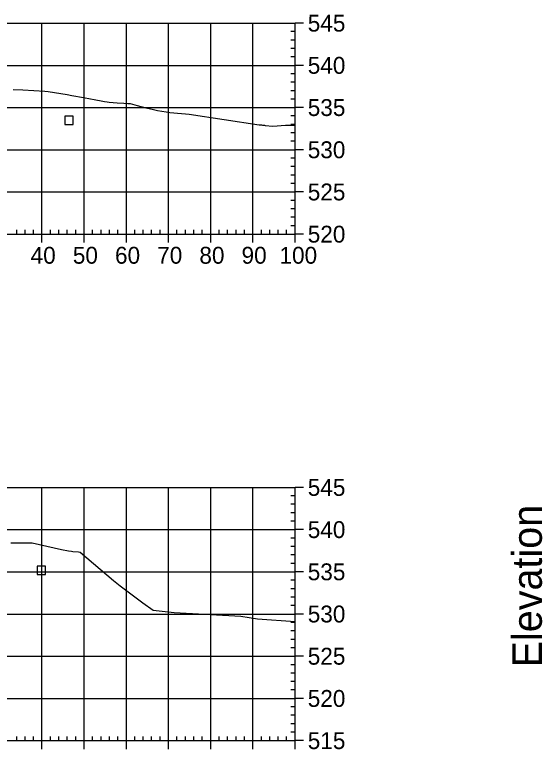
# Model space of a CAD drawing. Extents: x 704834 to 709892, y 372981 to 377533.
# Drawn here: x 707063.4 to 707188.5, y 377088.8 to 377262.8 of the extents above; entities that cross this region are included whole.
import ezdxf

# ---------------------------------------------------------------- set-up
doc = ezdxf.new("R2010")
doc.units = 0
for name, color, linetype in [('4', 7, 'Continuous'), ('57', 7, 'Continuous'), ('60', 7, 'Continuous'), ('Existing', 7, 'Continuous')]:
    doc.layers.add(name, color=color, linetype=linetype)

msp = doc.modelspace()

# ---------------------------------------------------------------- linework, layer by layer
at = {"layer": '4'}
for points in [[(707075.29, 377236.8), (707077.29, 377236.8), (707077.29, 377238.8), (707075.29, 377238.8)], [(707068.74, 377130.17), (707070.74, 377130.17), (707070.74, 377132.17), (707068.74, 377132.17)]]:
    msp.add_lwpolyline(points, close=True, dxfattribs=at)
at = {"layer": '57'}
for p, q in [((706929.91, 377260.82), (707129.91, 377260.82)), ((707069.91, 377210.82), (707069.91, 377260.82)), ((707079.91, 377210.82), (707079.91, 377260.82)), ((707089.91, 377210.82), (707089.91, 377260.82)), ((707099.91, 377210.82), (707099.91, 377260.82)), ((707109.91, 377210.82), (707109.91, 377260.82)), ((707119.91, 377210.82), (707119.91, 377260.82)), ((707129.91, 377210.82), (707129.91, 377260.82)), ((707129.91, 377210.82), (707129.91, 377260.82)), ((707131.91, 377260.82), (707129.91, 377260.82)), ((707129.91, 377258.82), (707128.91, 377258.82)), ((707129.91, 377256.82), (707128.91, 377256.82)), ((707129.91, 377254.82), (707128.91, 377254.82)), ((707129.91, 377252.82), (707128.91, 377252.82)), ((706929.91, 377250.82), (707129.91, 377250.82)), ((707131.91, 377250.82), (707129.91, 377250.82)), ((707129.91, 377248.82), (707128.91, 377248.82)), ((707129.91, 377246.82), (707128.91, 377246.82)), ((707129.91, 377244.82), (707128.91, 377244.82)), ((707129.91, 377242.82), (707128.91, 377242.82)), ((706929.91, 377240.82), (707129.91, 377240.82)), ((707131.91, 377240.82), (707129.91, 377240.82)), ((707129.91, 377238.82), (707128.91, 377238.82)), ((707129.91, 377236.82), (707128.91, 377236.82)), ((707129.91, 377234.82), (707128.91, 377234.82)), ((707129.91, 377232.82), (707128.91, 377232.82)), ((706929.91, 377230.82), (707129.91, 377230.82)), ((707131.91, 377230.82), (707129.91, 377230.82)), ((707129.91, 377228.82), (707128.91, 377228.82)), ((707129.91, 377226.82), (707128.91, 377226.82)), ((707129.91, 377224.82), (707128.91, 377224.82)), ((707129.91, 377222.82), (707128.91, 377222.82)), ((706929.91, 377220.82), (707129.91, 377220.82)), ((707131.91, 377220.82), (707129.91, 377220.82)), ((707129.91, 377218.82), (707128.91, 377218.82)), ((707129.91, 377216.82), (707128.91, 377216.82)), ((707129.91, 377214.82), (707128.91, 377214.82)), ((707129.91, 377212.82), (707128.91, 377212.82)), ((706929.91, 377210.82), (707129.91, 377210.82)), ((706929.91, 377210.82), (707129.91, 377210.82)), ((707063.91, 377210.82), (707063.91, 377211.82)), ((707065.91, 377210.82), (707065.91, 377211.82)), ((707067.91, 377210.82), (707067.91, 377211.82)), ((707069.91, 377208.82), (707069.91, 377210.82)), ((707071.91, 377210.82), (707071.91, 377211.82)), ((707073.91, 377210.82), (707073.91, 377211.82)), ((707075.91, 377210.82), (707075.91, 377211.82)), ((707077.91, 377210.82), (707077.91, 377211.82)), ((707079.91, 377208.82), (707079.91, 377210.82)), ((707081.91, 377210.82), (707081.91, 377211.82)), ((707083.91, 377210.82), (707083.91, 377211.82)), ((707085.91, 377210.82), (707085.91, 377211.82)), ((707087.91, 377210.82), (707087.91, 377211.82)), ((707089.91, 377208.82), (707089.91, 377210.82)), ((707091.91, 377210.82), (707091.91, 377211.82)), ((707093.91, 377210.82), (707093.91, 377211.82)), ((707095.91, 377210.82), (707095.91, 377211.82)), ((707097.91, 377210.82), (707097.91, 377211.82)), ((707099.91, 377208.82), (707099.91, 377210.82)), ((707101.91, 377210.82), (707101.91, 377211.82)), ((707103.91, 377210.82), (707103.91, 377211.82)), ((707105.91, 377210.82), (707105.91, 377211.82)), ((707107.91, 377210.82), (707107.91, 377211.82)), ((707109.91, 377208.82), (707109.91, 377210.82)), ((707111.91, 377210.82), (707111.91, 377211.82)), ((707113.91, 377210.82), (707113.91, 377211.82)), ((707115.91, 377210.82), (707115.91, 377211.82)), ((707117.91, 377210.82), (707117.91, 377211.82)), ((707119.91, 377208.82), (707119.91, 377210.82)), ((707121.91, 377210.82), (707121.91, 377211.82)), ((707123.91, 377210.82), (707123.91, 377211.82)), ((707125.91, 377210.82), (707125.91, 377211.82)), ((707127.91, 377210.82), (707127.91, 377211.82)), ((707129.91, 377208.82), (707129.91, 377210.82)), ((707131.91, 377210.82), (707129.91, 377210.82)), ((706929.91, 377150.82), (707129.91, 377150.82)), ((707069.91, 377090.82), (707069.91, 377150.82)), ((707079.91, 377090.82), (707079.91, 377150.82)), ((707089.91, 377090.82), (707089.91, 377150.82)), ((707099.91, 377090.82), (707099.91, 377150.82)), ((707109.91, 377090.82), (707109.91, 377150.82)), ((707119.91, 377090.82), (707119.91, 377150.82)), ((707129.91, 377090.82), (707129.91, 377150.82)), ((707129.91, 377090.82), (707129.91, 377150.82)), ((707131.91, 377150.82), (707129.91, 377150.82)), ((707129.91, 377148.82), (707128.91, 377148.82)), ((707129.91, 377146.82), (707128.91, 377146.82)), ((707129.91, 377144.82), (707128.91, 377144.82)), ((707129.91, 377142.82), (707128.91, 377142.82)), ((706929.91, 377140.82), (707129.91, 377140.82)), ((707131.91, 377140.82), (707129.91, 377140.82)), ((707129.91, 377138.82), (707128.91, 377138.82)), ((707129.91, 377136.82), (707128.91, 377136.82)), ((707129.91, 377134.82), (707128.91, 377134.82)), ((707129.91, 377132.82), (707128.91, 377132.82)), ((706929.91, 377130.82), (707129.91, 377130.82)), ((707131.91, 377130.82), (707129.91, 377130.82)), ((707129.91, 377128.82), (707128.91, 377128.82)), ((707129.91, 377126.82), (707128.91, 377126.82)), ((707129.91, 377124.82), (707128.91, 377124.82)), ((707129.91, 377122.82), (707128.91, 377122.82)), ((706929.91, 377120.82), (707129.91, 377120.82)), ((707131.91, 377120.82), (707129.91, 377120.82)), ((707129.91, 377118.82), (707128.91, 377118.82)), ((707129.91, 377116.82), (707128.91, 377116.82)), ((707129.91, 377114.82), (707128.91, 377114.82)), ((707129.91, 377112.82), (707128.91, 377112.82)), ((706929.91, 377110.82), (707129.91, 377110.82)), ((707131.91, 377110.82), (707129.91, 377110.82)), ((707129.91, 377108.82), (707128.91, 377108.82)), ((707129.91, 377106.82), (707128.91, 377106.82)), ((707129.91, 377104.82), (707128.91, 377104.82)), ((707129.91, 377102.82), (707128.91, 377102.82)), ((706929.91, 377100.82), (707129.91, 377100.82)), ((707131.91, 377100.82), (707129.91, 377100.82)), ((707129.91, 377098.82), (707128.91, 377098.82)), ((707129.91, 377096.82), (707128.91, 377096.82)), ((707129.91, 377094.82), (707128.91, 377094.82)), ((707129.91, 377092.82), (707128.91, 377092.82)), ((706929.91, 377090.82), (707129.91, 377090.82)), ((706929.91, 377090.82), (707129.91, 377090.82)), ((707063.91, 377090.82), (707063.91, 377091.82)), ((707065.91, 377090.82), (707065.91, 377091.82)), ((707067.91, 377090.82), (707067.91, 377091.82)), ((707069.91, 377088.82), (707069.91, 377090.82)), ((707071.91, 377090.82), (707071.91, 377091.82)), ((707073.91, 377090.82), (707073.91, 377091.82)), ((707075.91, 377090.82), (707075.91, 377091.82)), ((707077.91, 377090.82), (707077.91, 377091.82)), ((707079.91, 377088.82), (707079.91, 377090.82)), ((707081.91, 377090.82), (707081.91, 377091.82)), ((707083.91, 377090.82), (707083.91, 377091.82)), ((707085.91, 377090.82), (707085.91, 377091.82)), ((707087.91, 377090.82), (707087.91, 377091.82)), ((707089.91, 377088.82), (707089.91, 377090.82)), ((707091.91, 377090.82), (707091.91, 377091.82)), ((707093.91, 377090.82), (707093.91, 377091.82)), ((707095.91, 377090.82), (707095.91, 377091.82)), ((707097.91, 377090.82), (707097.91, 377091.82)), ((707099.91, 377088.82), (707099.91, 377090.82)), ((707101.91, 377090.82), (707101.91, 377091.82)), ((707103.91, 377090.82), (707103.91, 377091.82)), ((707105.91, 377090.82), (707105.91, 377091.82)), ((707107.91, 377090.82), (707107.91, 377091.82)), ((707109.91, 377088.82), (707109.91, 377090.82)), ((707111.91, 377090.82), (707111.91, 377091.82)), ((707113.91, 377090.82), (707113.91, 377091.82)), ((707115.91, 377090.82), (707115.91, 377091.82)), ((707117.91, 377090.82), (707117.91, 377091.82)), ((707119.91, 377088.82), (707119.91, 377090.82)), ((707121.91, 377090.82), (707121.91, 377091.82)), ((707123.91, 377090.82), (707123.91, 377091.82)), ((707125.91, 377090.82), (707125.91, 377091.82)), ((707127.91, 377090.82), (707127.91, 377091.82)), ((707129.91, 377088.82), (707129.91, 377090.82)), ((707131.91, 377090.82), (707129.91, 377090.82))]:
    msp.add_line(p, q, dxfattribs=at)
at = {"layer": 'Existing'}
for points in [[(707063.04, 377245.06), (707065.4, 377244.98), (707070.6, 377244.68), (707071.35, 377244.64), (707075.85, 377243.88), (707076.99, 377243.66), (707079.74, 377243.21), (707081.42, 377242.89), (707082.25, 377242.75), (707084.31, 377242.37), (707084.71, 377242.29), (707085.37, 377242.18), (707085.86, 377242.12), (707086.78, 377242.01), (707087.77, 377241.92), (707089.31, 377241.83), (707090.27, 377241.78), (707090.84, 377241.76), (707092.47, 377241.31), (707094.51, 377240.78), (707096.05, 377240.42), (707097.3, 377240.15), (707098.36, 377239.95), (707099.31, 377239.8), (707100.22, 377239.68), (707101.15, 377239.57), (707102.05, 377239.49), (707103, 377239.41), (707103.95, 377239.34), (707104.83, 377239.28), (707121.41, 377236.75), (707121.67, 377236.73), (707121.92, 377236.71), (707122.16, 377236.68), (707122.4, 377236.65), (707122.62, 377236.62), (707122.82, 377236.59), (707124.64, 377236.44), (707127.66, 377236.63), (707129.91, 377236.63)], [(707062.56, 377137.66), (707067.59, 377137.65), (707074.52, 377136.11), (707076.2, 377135.77), (707076.91, 377135.68), (707077.23, 377135.65), (707078.6, 377135.52), (707078.96, 377135.47), (707086.86, 377128.79), (707088.47, 377127.48), (707093.81, 377123.5), (707096.3, 377121.72), (707101.23, 377121.21), (707117.08, 377120.33), (707121.03, 377119.7), (707129.91, 377119.01)]]:
    msp.add_lwpolyline(points, dxfattribs=at)

# ---------------------------------------------------------------- texts
at = {"layer": '57'}
for s, p in [('545', (707132.91, 377258.82)), ('540', (707132.91, 377248.82)), ('535', (707132.91, 377238.82)), ('530', (707132.91, 377228.82)), ('525', (707132.91, 377218.82)), ('520', (707132.91, 377208.82)), ('40', (707067.22, 377203.82)), ('50', (707077.22, 377203.82)), ('60', (707087.22, 377203.82)), ('70', (707097.22, 377203.82)), ('80', (707107.22, 377203.82)), ('90', (707117.22, 377203.82)), ('100', (707126.21, 377203.82)), ('545', (707132.91, 377148.82)), ('540', (707132.91, 377138.82)), ('535', (707132.91, 377128.82)), ('530', (707132.91, 377118.82)), ('525', (707132.91, 377108.82)), ('520', (707132.91, 377098.82)), ('515', (707132.91, 377088.82))]:
    msp.add_text(s, height=4, dxfattribs=at).set_placement(p)
at = {"layer": '60'}
msp.add_text('Elevation', height=7, rotation=90, dxfattribs=at).set_placement((707188.41, 377108.18))

doc.saveas('drawing.dxf')
